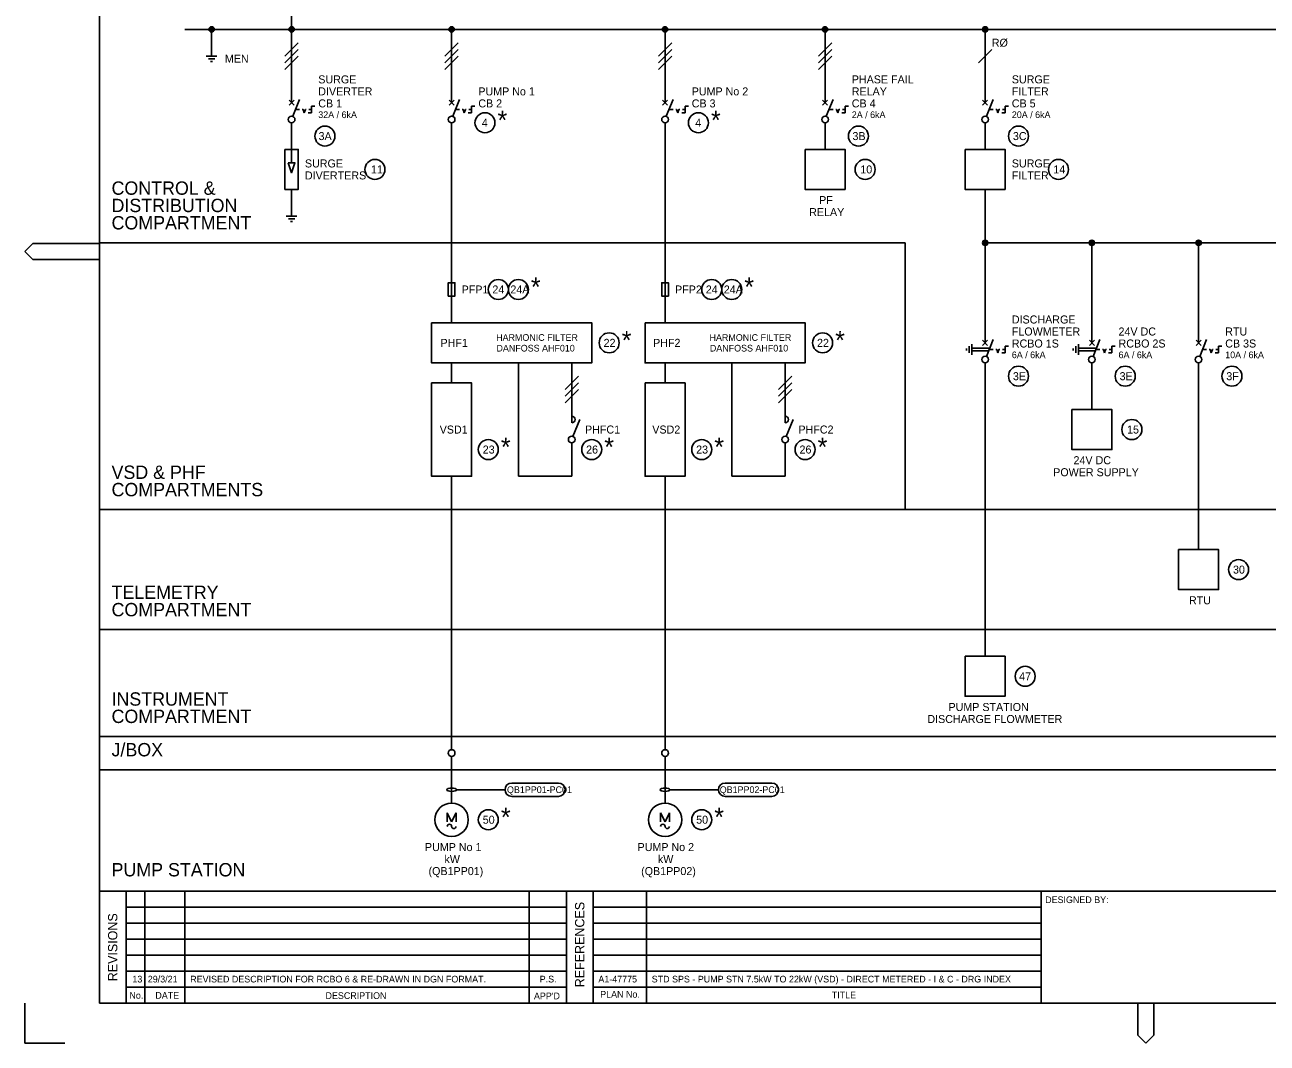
# Model space of a CAD drawing. Extents: x 0 to 841, y 0 to 594.
# Drawn here: x 0 to 465.7, y 0 to 381.7 of the extents above; entities that cross this region are included whole.
import ezdxf

# ---------------------------------------------------------------- set-up
doc = ezdxf.new("R2010")
doc.units = 0
for name, color, linetype in [('A1BORDER', 7, 'Continuous'), ('BASE', 7, 'Continuous'), ('Level 1', 7, 'Continuous'), ('Level 10', 7, 'Continuous')]:
    doc.layers.add(name, color=color, linetype=linetype)

msp = doc.modelspace()

# ---------------------------------------------------------------- linework, layer by layer
at = {"layer": 'A1BORDER'}
for p, q in [((28, 581), (28, 15)), ((3, 299.76), (0, 296.76)), ((28, 299.76), (3, 299.76)), ((3, 293.76), (0, 296.76)), ((28, 293.76), (3, 293.76)), ((28, 57), (829, 57)), ((38, 15), (38, 57)), ((45, 15), (45, 57)), ((60, 15), (60, 57)), ((189, 15), (189, 57)), ((203, 15), (203, 57)), ((213, 15), (213, 57)), ((233, 15), (233, 57)), ((381, 15), (381, 57)), ((203, 51), (38, 51)), ((213, 51), (381, 51)), ((203, 45), (38, 45)), ((213, 45), (381, 45)), ((203, 39), (38, 39)), ((213, 39), (381, 39)), ((203, 33), (38, 33)), ((213, 33), (381, 33)), ((38, 27), (203, 27)), ((213, 27), (381, 27)), ((203, 21), (38, 21)), ((213, 21), (381, 21)), ((0, 0), (0, 15)), ((829, 15), (28, 15)), ((417.19, 15), (417.19, 3)), ((423.19, 15), (423.19, 3)), ((417.19, 3), (420.19, 0)), ((423.19, 3), (420.19, 0)), ((0, 0), (15, 0))]:
    msp.add_line(p, q, dxfattribs=at)
at = {"layer": 'BASE'}
for p, q in [((161.875, 95), (180, 95)), ((241.875, 95), (260, 95))]:
    msp.add_line(p, q, dxfattribs=at)
for points in [[(200, 97.5), (182.5, 97.5)], [(280, 97.5), (262.5, 97.5)], [(182.5, 92.5), (200, 92.5)], [(262.5, 92.5), (280, 92.5)]]:
    msp.add_lwpolyline(points, dxfattribs=at)
for centre, start, end in [((182.5, 95), 90, 270), ((200, 95), 270, 90), ((262.5, 95), 90, 270), ((280, 95), 270, 90)]:
    msp.add_arc(centre, 2.5, start, end, dxfattribs=at)
for centre in [(160, 95), (240, 95)]:
    msp.add_ellipse(centre, major_axis=(1.875, 0), ratio=0.333333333, dxfattribs=at)
at = {"layer": 'Level 1'}
for p, q in [((100, 352.5), (100, 402.5)), ((60, 380), (792.5, 380)), ((70, 380), (70, 370)), ((160, 380), (160, 352.5)), ((240, 380), (240, 352.5)), ((300, 380), (300, 352.5)), ((360, 380), (360, 355)), ((97.5, 370), (102.5, 375)), ((157.5, 370), (162.5, 375)), ((237.5, 370), (242.5, 375)), ((297.5, 370), (302.5, 375)), ((97.5, 367.5), (102.5, 372.5)), ((97.5, 365), (102.5, 370)), ((157.5, 367.5), (162.5, 372.5)), ((157.5, 365), (162.5, 370)), ((237.5, 367.5), (242.5, 372.5)), ((237.5, 365), (242.5, 370)), ((297.5, 367.5), (302.5, 372.5)), ((297.5, 365), (302.5, 370)), ((357.5, 367.5), (362.5, 372.5)), ((100, 352.5), (100, 355)), ((160, 352.5), (160, 355)), ((240, 352.5), (240, 355)), ((300, 352.5), (300, 355)), ((360, 352.5), (360, 355)), ((99.06, 353.44), (100.94, 351.56)), ((100.94, 353.44), (99.06, 351.56)), ((100.46, 347.41), (103, 353.75)), ((159.06, 353.44), (160.94, 351.56)), ((160.94, 353.44), (159.06, 351.56)), ((160.46, 347.41), (163, 353.75)), ((239.06, 353.44), (240.94, 351.56)), ((240.94, 353.44), (239.06, 351.56)), ((240.46, 347.41), (243, 353.75)), ((299.06, 353.44), (300.94, 351.56)), ((300.94, 353.44), (299.06, 351.56)), ((300.46, 347.41), (303, 353.75)), ((359.06, 353.44), (360.94, 351.56)), ((360.94, 353.44), (359.06, 351.56)), ((360.46, 347.41), (363, 353.75)), ((100, 345), (100, 330)), ((160, 345), (160, 270)), ((240, 345), (240, 270)), ((300, 345), (300, 335)), ((360, 345), (360, 335)), ((100, 320), (100, 310)), ((360, 320), (360, 265)), ((330, 300), (28, 300)), ((330, 300), (330, 200)), ((520, 300), (360, 300)), ((400, 300), (400, 265)), ((440, 300), (440, 265)), ((359.06, 263.44), (360.94, 261.56)), ((360.94, 263.44), (359.06, 261.56)), ((360, 262.5), (360, 265)), ((360.46, 257.41), (363, 263.75)), ((399.06, 263.44), (400.94, 261.56)), ((400.94, 263.44), (399.06, 261.56)), ((400, 262.5), (400, 265)), ((400.46, 257.41), (403, 263.75)), ((439.06, 263.44), (440.94, 261.56)), ((440.94, 263.44), (439.06, 261.56)), ((440, 262.5), (440, 265)), ((440.46, 257.41), (443, 263.75)), ((355, 260.5), (361.69795, 260.5)), ((355, 259.5), (361.29732, 259.5)), ((395, 260.5), (401.69795, 260.5)), ((395, 259.5), (401.29732, 259.5)), ((160, 255), (160, 247.5)), ((185, 212.5), (185, 255)), ((205, 255), (205, 235)), ((240, 247.5), (240, 255)), ((265, 212.5), (265, 255)), ((285, 255), (285, 235)), ((360, 255), (360, 145)), ((400, 255), (400, 237.5)), ((440, 255), (440, 185)), ((202.5, 245), (207.5, 250)), ((202.5, 242.5), (207.5, 247.5)), ((282.5, 245), (287.5, 250)), ((282.5, 242.5), (287.5, 247.5)), ((202.5, 240), (207.5, 245)), ((282.5, 240), (287.5, 245)), ((205, 232.5), (205, 235)), ((205.46, 227.41), (208, 233.75)), ((285, 232.5), (285, 235)), ((285.46, 227.41), (288, 233.75)), ((205, 225), (205, 212.5)), ((285, 225), (285, 212.5)), ((160, 212.5), (160, 110)), ((205, 212.5), (185, 212.5)), ((240, 212.5), (240, 110)), ((285, 212.5), (265, 212.5)), ((829, 200), (28, 200)), ((829, 155), (28, 155)), ((829, 115), (28, 115)), ((160, 107.5), (160, 90)), ((240, 107.5), (240, 90)), ((829, 102.5), (28, 102.5))]:
    msp.add_line(p, q, dxfattribs=at)
for points in [[(97.5, 335), (102.5, 335), (102.5, 320), (97.5, 320)], [(292.5, 335), (307.5, 335), (307.5, 320), (292.5, 320)], [(352.5, 335), (367.5, 335), (367.5, 320), (352.5, 320)], [(98.75, 330), (100, 326.25), (101.25, 330)], [(152.5, 270), (212.5, 270), (212.5, 255), (152.5, 255)], [(232.5, 270), (292.5, 270), (292.5, 255), (232.5, 255)], [(152.5, 247.5), (167.5, 247.5), (167.5, 212.5), (152.5, 212.5)], [(232.5, 247.5), (247.5, 247.5), (247.5, 212.5), (232.5, 212.5)], [(392.5, 237.5), (407.5, 237.5), (407.5, 222.5), (392.5, 222.5)], [(432.5, 185), (447.5, 185), (447.5, 170), (432.5, 170)], [(352.5, 145), (367.5, 145), (367.5, 130), (352.5, 130)]]:
    msp.add_lwpolyline(points, close=True, dxfattribs=at)
for centre, radius in [((100, 346.25), 1.25), ((160, 346.25), 1.25), ((172.5, 345), 3.75), ((240, 346.25), 1.25), ((252.5, 345), 3.75), ((300, 346.25), 1.25), ((360, 346.25), 1.25), ((112.5, 340), 3.75), ((312.5, 340), 3.75), ((372.5, 340), 3.75), ((131.25, 327.5), 3.75), ((315, 327.5), 3.75), ((387.5, 327.5), 3.75), ((177.5, 282.5), 3.75), ((185, 282.5), 3.75), ((257.5, 282.5), 3.75), ((265, 282.5), 3.75), ((219.06129, 262.5), 3.75), ((299.06129, 262.5), 3.75), ((360, 256.25), 1.25), ((400, 256.25), 1.25), ((440, 256.25), 1.25), ((372.5, 250), 3.75), ((412.5, 250), 3.75), ((452.5, 250), 3.75), ((415, 230), 3.75), ((173.75, 222.5), 3.75), ((205, 226.25), 1.25), ((212.5, 222.5), 3.75), ((253.75, 222.5), 3.75), ((285, 226.25), 1.25), ((292.5, 222.5), 3.75), ((455, 177.5), 3.75), ((375, 137.5), 3.75), ((160, 108.75), 1.25), ((240, 108.75), 1.25), ((173.75, 83.75), 3.75), ((253.75, 83.75), 3.75)]:
    msp.add_circle(centre, radius, dxfattribs=at)
for centre in [(205, 233.75), (285, 233.75)]:
    msp.add_arc(centre, 1.25, 270, 90, dxfattribs=at)
at = {"layer": 'Level 10'}
for p, q in [((69, 380), (70.99, 380)), ((69.05, 380.3), (70.95, 380.3)), ((69.05, 379.7), (70.95, 379.7)), ((69.2, 380.6), (70.8, 380.6)), ((69.2, 379.4), (70.8, 379.4)), ((69.56, 380.9), (70.44, 380.9)), ((69.56, 379.1), (70.44, 379.1)), ((70, 381), (70, 381)), ((99, 380), (100.99, 380)), ((99.05, 380.3), (100.95, 380.3)), ((99.05, 379.7), (100.95, 379.7)), ((99.2, 380.6), (100.8, 380.6)), ((99.2, 379.4), (100.8, 379.4)), ((99.56, 380.9), (100.44, 380.9)), ((99.56, 379.1), (100.44, 379.1)), ((100, 381), (100, 381)), ((159.01, 380.1), (160.99, 380.1)), ((159.02, 379.8), (160.98, 379.8)), ((159.08, 380.4), (160.92, 380.4)), ((159.13, 379.5), (160.87, 379.5)), ((159.29, 380.7), (160.71, 380.7)), ((159.4, 379.2), (160.6, 379.2)), ((160, 381), (160, 381)), ((239.01, 380.1), (240.99, 380.1)), ((239.02, 379.8), (240.98, 379.8)), ((239.08, 380.4), (240.92, 380.4)), ((239.13, 379.5), (240.87, 379.5)), ((239.29, 380.7), (240.71, 380.7)), ((239.4, 379.2), (240.6, 379.2)), ((240, 381), (240, 381)), ((299.01, 380.1), (300.99, 380.1)), ((299.02, 379.8), (300.98, 379.8)), ((299.08, 380.4), (300.92, 380.4)), ((299.13, 379.5), (300.87, 379.5)), ((299.29, 380.7), (300.71, 380.7)), ((299.4, 379.2), (300.6, 379.2)), ((300, 381), (300, 381)), ((359.01, 380.1), (360.99, 380.1)), ((359.02, 379.8), (360.98, 379.8)), ((359.08, 380.4), (360.92, 380.4)), ((359.13, 379.5), (360.87, 379.5)), ((359.29, 380.7), (360.71, 380.7)), ((359.4, 379.2), (360.6, 379.2)), ((360, 381), (360, 381)), ((68, 370), (72, 370)), ((68.8, 369), (71.2, 369)), ((69.6, 368), (70.4, 368)), ((101.5, 350), (103, 350)), ((104, 350), (104.33, 350)), ((104.75, 348.75), (104.33, 350)), ((104.75, 348.75), (105.17, 350)), ((105.5, 350), (105.17, 350)), ((106.5, 350), (107.5, 350)), ((107.5, 348.75), (107.5, 351.25)), ((107.5, 351.25), (108.75, 351.25)), ((161.5, 350), (163, 350)), ((164, 350), (164.33, 350)), ((164.75, 348.75), (164.33, 350)), ((164.75, 348.75), (165.17, 350)), ((165.5, 350), (165.17, 350)), ((166.5, 350), (167.5, 350)), ((167.5, 348.75), (167.5, 351.25)), ((167.5, 351.25), (168.75, 351.25)), ((241.5, 350), (243, 350)), ((244, 350), (244.33, 350)), ((244.75, 348.75), (244.33, 350)), ((244.75, 348.75), (245.17, 350)), ((245.5, 350), (245.17, 350)), ((246.5, 350), (247.5, 350)), ((247.5, 348.75), (247.5, 351.25)), ((247.5, 351.25), (248.75, 351.25)), ((301.5, 350), (303, 350)), ((304, 350), (304.33, 350)), ((304.75, 348.75), (304.33, 350)), ((304.75, 348.75), (305.17, 350)), ((305.5, 350), (305.17, 350)), ((306.5, 350), (307.5, 350)), ((307.5, 348.75), (307.5, 351.25)), ((307.5, 351.25), (308.75, 351.25)), ((361.5, 350), (363, 350)), ((364, 350), (364.33, 350)), ((364.75, 348.75), (364.33, 350)), ((364.75, 348.75), (365.17, 350)), ((365.5, 350), (365.17, 350)), ((366.5, 350), (367.5, 350)), ((367.5, 348.75), (367.5, 351.25)), ((367.5, 351.25), (368.75, 351.25)), ((106.25, 348.75), (107.5, 348.75)), ((166.25, 348.75), (167.5, 348.75)), ((246.25, 348.75), (247.5, 348.75)), ((306.25, 348.75), (307.5, 348.75)), ((366.25, 348.75), (367.5, 348.75)), ((98, 310), (102, 310)), ((98.8, 309), (101.2, 309)), ((99.6, 308), (100.4, 308)), ((359.01, 300.1), (360.99, 300.1)), ((359.02, 299.8), (360.98, 299.8)), ((359.08, 300.4), (360.92, 300.4)), ((359.13, 299.5), (360.87, 299.5)), ((359.29, 300.7), (360.71, 300.7)), ((359.4, 299.2), (360.6, 299.2)), ((360, 301), (360, 301)), ((399.01, 300.1), (400.99, 300.1)), ((399.02, 299.8), (400.98, 299.8)), ((399.08, 300.4), (400.92, 300.4)), ((399.13, 299.5), (400.87, 299.5)), ((399.29, 300.7), (400.71, 300.7)), ((399.4, 299.2), (400.6, 299.2)), ((400, 301), (400, 301)), ((439.01, 300.1), (440.99, 300.1)), ((439.02, 299.8), (440.98, 299.8)), ((439.08, 300.4), (440.92, 300.4)), ((439.13, 299.5), (440.87, 299.5)), ((439.29, 300.7), (440.71, 300.7)), ((439.4, 299.2), (440.6, 299.2)), ((440, 301), (440, 301)), ((354, 261.2), (354, 258.8)), ((355, 262), (355, 258)), ((367.5, 258.75), (367.5, 261.25)), ((367.5, 261.25), (368.75, 261.25)), ((394, 261.2), (394, 258.8)), ((395, 262), (395, 258)), ((407.5, 258.75), (407.5, 261.25)), ((407.5, 261.25), (408.75, 261.25)), ((447.5, 258.75), (447.5, 261.25)), ((447.5, 261.25), (448.75, 261.25)), ((353, 260.4), (353, 259.6)), ((361.5, 260), (363, 260)), ((364, 260), (364.33, 260)), ((364.75, 258.75), (364.33, 260)), ((364.75, 258.75), (365.17, 260)), ((365.5, 260), (365.17, 260)), ((366.25, 258.75), (367.5, 258.75)), ((366.5, 260), (367.5, 260)), ((393, 260.4), (393, 259.6)), ((401.5, 260), (403, 260)), ((404, 260), (404.33, 260)), ((404.75, 258.75), (404.33, 260)), ((404.75, 258.75), (405.17, 260)), ((405.5, 260), (405.17, 260)), ((406.25, 258.75), (407.5, 258.75)), ((406.5, 260), (407.5, 260)), ((441.5, 260), (443, 260)), ((444, 260), (444.33, 260)), ((444.75, 258.75), (444.33, 260)), ((444.75, 258.75), (445.17, 260)), ((445.5, 260), (445.17, 260)), ((446.25, 258.75), (447.5, 258.75)), ((446.5, 260), (447.5, 260)), ((158.33, 86.33), (160, 83)), ((158.33, 83), (158.33, 86.33)), ((160, 83), (161.67, 86.33)), ((161.67, 86.33), (161.67, 83)), ((238.33, 86.33), (240, 83)), ((238.33, 83), (238.33, 86.33)), ((240, 83), (241.67, 86.33)), ((241.67, 86.33), (241.67, 83))]:
    msp.add_line(p, q, dxfattribs=at)
for points in [[(160, 280), (161.25, 280), (161.25, 285), (158.75, 285), (158.75, 280), (160, 280)], [(240, 280), (241.25, 280), (241.25, 285), (238.75, 285), (238.75, 280), (240, 280)]]:
    msp.add_lwpolyline(points, dxfattribs=at)
for centre, radius in [((70, 380), 1), ((100, 380), 1), ((160, 380), 1), ((240, 380), 1), ((300, 380), 1), ((360, 380), 1), ((360, 300), 1), ((400, 300), 1), ((440, 300), 1), ((160, 83.75), 6.25), ((240, 83.75), 6.25)]:
    msp.add_circle(centre, radius, dxfattribs=at)
for centre, start, end in [((159.17, 81.25), 0, 180), ((160.83, 81.25), 180, 0), ((239.17, 81.25), 0, 180), ((240.83, 81.25), 180, 0)]:
    msp.add_arc(centre, 0.83, start, end, dxfattribs=at)

# ---------------------------------------------------------------- texts
at = {"layer": 'A1BORDER'}
for s, p in [('REFERENCES', (209.76, 20.96)), ('REVISIONS', (34.68, 23.2))]:
    msp.add_text(s, height=3.49998, rotation=90, dxfattribs=at).set_placement(p)
for s, height, p in [('DESIGNED BY:', 2.5, (382.5, 52.5)), ('No.', 2.50002, (39.21, 16.65)), ('DATE', 2.50002, (48.92, 16.65)), ('DESCRIPTION', 2.50002, (112.71, 16.57)), ("APP'D", 2.50002, (190.85, 16.44)), ('PLAN No.', 2.50002, (215.69, 17.06)), ('TITLE', 2.50002, (302.5, 16.81))]:
    msp.add_text(s, height=height, dxfattribs=at).set_placement(p)
at = {"layer": 'BASE'}
for s, p in [('QB1PP01-PC01', (180.75, 93.75)), ('QB1PP02-PC01', (260.5, 93.75))]:
    msp.add_text(s, height=2.5, dxfattribs=at).set_placement(p)
at = {"layer": 'Level 1'}
for s, height, p in [('R%%C', 3, (362.5, 373.5)), ('MEN', 3, (75, 367.5)), ('SURGE', 3, (110, 359.75)), ('PHASE FAIL', 3, (310, 359.75)), ('SURGE', 3, (370, 359.75)), ('DIVERTER', 3, (110, 355.25)), ('PUMP No 1', 3, (170, 355.25)), ('PUMP No 2', 3, (250, 355.25)), ('RELAY', 3, (310, 355.25)), ('FILTER', 3, (370, 355.25)), ('32A / 6kA', 2.50002, (110, 346.75)), ('CB 1', 3, (110, 350.75)), ('CB 2', 3, (170, 350.75)), ('*', 7, (177.21094, 342.5)), ('CB 3', 3, (250, 350.75)), ('*', 7, (257.21094, 342.5)), ('2A / 6kA', 2.50002, (310, 346.75)), ('CB 4', 3, (310, 350.75)), ('20A / 6kA', 2.50002, (370, 346.75)), ('CB 5', 3, (370, 350.75)), ('4', 3, (171.30469, 343.5)), ('4', 3, (251.30469, 343.5)), ('3A', 3, (110.10938, 338.5)), ('3B', 3, (310.25879, 338.5)), ('3C', 3, (370.4082, 338.5)), ('SURGE', 3, (105, 328.25)), ('SURGE', 3, (370, 328.25)), ('DIVERTERS', 3, (105, 323.75)), ('11', 3, (129.75586, 326)), ('10', 3, (313.20703, 326)), ('FILTER', 3, (370, 323.75)), ('14', 3, (385.55762, 326)), ('CONTROL &', 5, (32.5, 318)), ('PF', 3, (297.75879, 314.5)), ('DISTRIBUTION', 5, (32.5, 311.5)), ('RELAY', 3, (294.02344, 310)), ('COMPARTMENT', 5, (32.5, 305)), ('*', 7, (189.71094, 280)), ('*', 7, (269.71094, 280)), ('PFP1', 3, (163.75, 281)), ('24', 3, (175.25879, 281)), ('24A', 3, (182.01172, 281)), ('PFP2', 3, (243.75, 281)), ('24', 3, (255.25879, 281)), ('24A', 3, (262.01172, 281)), ('DISCHARGE', 3, (370, 269.75)), ('HARMONIC FILTER', 2.50002, (176.67714, 263.25)), ('*', 7, (223.77223, 260)), ('HARMONIC FILTER', 2.50002, (256.67714, 263.25)), ('*', 7, (303.77223, 260)), ('FLOWMETER', 3, (370, 265.25)), ('24V DC', 3, (410, 265.25)), ('RTU', 3, (450, 265.25)), ('PHF1', 3, (155.81641, 261)), ('DANFOSS AHF010', 2.50002, (176.80165, 259.24998)), ('22', 3, (216.96949, 261)), ('PHF2', 3, (235.51758, 261)), ('DANFOSS AHF010', 2.50002, (256.80165, 259.24998)), ('22', 3, (296.96949, 261)), ('RCBO 1S', 3, (370, 260.75)), ('RCBO 2S', 3, (410, 260.75)), ('CB 3S', 3, (450, 260.75)), ('6A / 6kA', 2.50002, (370, 256.75)), ('6A / 6kA', 2.50002, (410, 256.75)), ('10A / 6kA', 2.50002, (450, 256.75)), ('3E', 3, (370.4082, 248.5)), ('3E', 3, (410.4082, 248.5)), ('3F', 3, (450.4082, 248.5)), ('VSD1', 3, (155.51758, 228.5)), ('PHFC1', 3, (210, 228.5)), ('VSD2', 3, (235.21875, 228.5)), ('PHFC2', 3, (290, 228.5)), ('15', 3, (413.20703, 228.5)), ('23', 3, (171.6582, 221)), ('*', 7, (178.46094, 220)), ('26', 3, (210.4082, 221)), ('*', 7, (217.21094, 220)), ('23', 3, (251.6582, 221)), ('*', 7, (258.46094, 220)), ('26', 3, (290.4082, 221)), ('*', 7, (297.21094, 220)), ('24V DC', 3, (393.12695, 217)), ('VSD & PHF', 5, (32.5, 211.5)), ('POWER SUPPLY', 3, (385.50684, 212.5)), ('COMPARTMENTS', 5, (32.5, 205)), ('30', 3, (452.9082, 176)), ('TELEMETRY', 5, (32.5, 166.5)), ('COMPARTMENT', 5, (32.5, 160)), ('RTU', 3, (436.41406, 164.5)), ('47', 3, (372.75879, 136)), ('INSTRUMENT', 5, (32.5, 126.5)), ('PUMP STATION', 3, (346.25391, 124.5)), ('COMPARTMENT', 5, (32.5, 120)), ('DISCHARGE FLOWMETER', 3, (338.33496, 120)), ('J/BOX', 5, (32.5, 107.5)), ('50', 3, (171.6582, 82.25)), ('*', 7, (178.46094, 81.25)), ('50', 3, (251.6582, 82.25)), ('*', 7, (258.46094, 81.25)), ('PUMP No 1', 3, (149.98926, 72)), ('PUMP No 2', 3, (229.69043, 72)), ('kW', 3, (157.31055, 67.5)), ('kW', 3, (237.31055, 67.5)), ('PUMP STATION', 5, (32.5, 62.5)), ('(QB1PP01)', 3, (151.33398, 63)), ('(QB1PP02)', 3, (231.03516, 63)), ('13', 2.50002, (40.31744, 22.75)), ('29/3/21', 2.50002, (46.09354, 22.75)), ('REVISED DESCRIPTION FOR RCBO 6 & RE-DRAWN IN DGN FORMAT.', 2.50002, (62, 22.75)), ('P.S.', 2.50002, (193.01549, 22.75)), ('A1-47775', 2.50002, (215, 22.75)), ('STD SPS - PUMP STN 7.5kW TO 22kW (VSD) - DIRECT METERED - I & C - DRG INDEX', 2.50002, (235, 22.75))]:
    msp.add_text(s, height=height, dxfattribs=at).set_placement(p)

doc.saveas('drawing.dxf')
